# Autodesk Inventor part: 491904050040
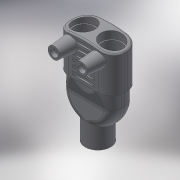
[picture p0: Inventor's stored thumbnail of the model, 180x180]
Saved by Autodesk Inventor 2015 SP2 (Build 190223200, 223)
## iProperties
Created: 2017-07
Part Number: 491904050040
Material: Generic
Description: PLASSON REDUCING Y 50X40X40
Document SubType Name: Modeling
Designer: KIM
Density: 1 g/cm^3
Appearance: Default
Author: KIM
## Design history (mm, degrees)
derived "491904.ipt"
feature "Solid1::491904.ipt"
tag "TaggingFeature1"
body "Solid1"
other parameters: "d0" = 108, "d1" = 123, "d2" = 24.6, "d3" = 10.8, "d4" = 98.4, "d5" = 64.8, "d6" = 56, "d7" = 0, "d8" = 36.9, "d9" = 36.9, "d10" = 25.2, "d11" = 2.8, "d12" = -24.6, "d13" = 25.2, "d14" = 43.2, "d15" = 61.5, "d16" = 0, "d17" = -4.92, "d18" = 4.92, "d19" = 0, "d22" = 9.225, "d34" = 54, "d35" = 27, "d36" = 46, "d37" = 0, "d38" = 44, "d39" = 44, "d40" = 11.5, "d41" = 0, "d42" = 36, "d43" = 180 deg, "d52" = 123, "d53" = 116.85, "d54" = 61.5, "d55" = 97.2, "d56" = 48.6, "d57" = 32.4, "d58" = 151, "d62" = 22.5, "d64" = 0, "d66" = 0.5, "d71" = 14.76, "d72" = 1.51, "d73" = 11, "d74" = 25, "d75" = 73.8, "d76" = 0, "d78" = 46, "d79" = 15, "d80" = 15, "d81" = 23.4, "d82" = 5 deg, "d83" = 4, "d84" = 4, "d87" = 14, "d88" = 0, "d89" = 4.53, "d90" = 3, "d91" = 0, "L_" = 56, "L_1" = 46, "H_1" = 123, "B_" = 108, "d_2" = 12, "H_" = 151, "A_" = 46
